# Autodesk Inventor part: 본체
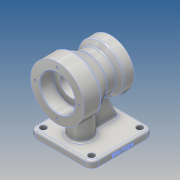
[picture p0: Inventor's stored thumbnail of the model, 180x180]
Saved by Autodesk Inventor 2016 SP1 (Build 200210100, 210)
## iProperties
Created: 2019-01
Part Number: 본체
Material: 알루미늄 6061
Document SubType Name: Modeling
Designer: Administrator
Density: 2.7 g/cm^3
Appearance: 알루미늄 - 평지
Mass: 898.821 g
Surface Area: 600.961 cm^2
Volume: 332.897 cm^3
Author: Administrator
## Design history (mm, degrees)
sketch "스케치2"
  geometry: L1 (0, 0)-(-80, 0); L2 (0, 0)-(0, 40); L3 (0, 40)-(-25, 40); L4 (-25, 40)-(-45.785, 28); L5 (-45.785, 28)-(-59.126, 28); L6 (-59.126, 28)-(-65, 35); L7 (-65, 35)-(-80, 35); L8 (-80, 35)-(-80, 0)
  constraints: 16 end point, 2 parallel, 2 perpendicular, 1 horizontal, 1 vertical
  dimensions: "d0" = 80 distance of L1.start L1.end; "d1" = 80 diameter of L3 L1; "d2" = 30 deg angle of L5 L4; "d3" = 50 deg angle of L5 L6; "d4" = 25 distance of L2.end L3.end; "d5" = 56 diameter of L5 L1; "d6" = 15 distance of L6.end L7.end; "d7" = 70 diameter of L7 L1
revolve "회전1" sketch "스케치2" stored, may be unused: angle "d8" = 90 deg
node "작업 평면1"
sketch "스케치4"
  geometry: L1 (5, 46)-(97, 46); L2 (97, 46)-(97, -46); L3 (97, -46)-(5, -46); L4 (5, -46)-(5, 46); 2 further points
  constraints: 8 end point, 2 parallel, 1 horizontal, 1 horizontal alignment, 1 midpoint, 1 perpendicular
  dimensions: "d12" = 92 distance of L2.end L3.end; "d13" = 92 distance of L1.end L2.end; "d14" = 5 distance from line of point (0, 0) L4
extrude "돌출1" join sketch "스케치4" distance "d15" = 10; taper "d16" = 0 deg
sketch "스케치5"
  geometry: L1 (50.199, 5)-(87, 5); L2 (87, 5)-(87, -5); L3 (87, -5)-(50.199, -5); L4 (5, -46)-(5, 46) reference; L5 (97, 46)-(97, -46) reference; A1 r 16 centre (35, 0) between (50.199, 5) and (50.199, -5); 2 further points
  constraints: 6 end point, 2 horizontal alignment, 2 point on circle, 1 centre point, 1 horizontal, 1 midpoint, 1 parallel, 1 perpendicular
  dimensions: "d17" = 32 diameter of A1; "d18" = 10 distance between parallel lines of L3 L1; "d19" = 30 distance from line of A1.centre L4; "d20" = 10 distance between parallel lines of L2 L5
extrude "돌출2" join sketch "스케치5" distance "d21" = 45; taper "d22" = 0 deg
feature "면 기울기2" dims angle "d26" = 25 deg
sketch "스케치7"
  geometry: L1 (0, 0)-(-80, 0); L2 (-80, -35)-(-80, 35) reference; L3 (0, -40)-(0, 40) reference; L4 (0, 26)-(-19, 26); L5 (-20, 25)-(-20, 16); L6 (-20, 16)-(-63, 16); L7 (-63, 16)-(-63, 19.4); L8 (-63.6, 20)-(-80, 20); L9 (0, 26)-(0, 0); L10 (-80, 20)-(-80, 0); A1 r 1 centre (-19, 25) between (-19, 26) and (-20, 25); A2 r 0.6 centre (-63.6, 19.4) between (-63, 19.4) and (-63.6, 20); 2 further points
  constraints: 16 end point, 6 point on line, 4 perpendicular, 4 point on circle, 4 tangent, 2 centre point, 1 collinear, 1 horizontal, 1 midpoint, 1 parallel
  dimensions: "d27" = 52 diameter of L4 L1; "d28" = 20 distance of L4.start point (-20, 26); "d29" = 32 diameter of L6 L1; "d30" = 17 distance of point (-63, 20) L8.end; "d31" = 40 diameter of L8 L1; "d32" = 1 radius of A1; "d33" = 0.6 radius of A2
revolve "회전2" sketch "스케치7" stored, may be unused: angle "d34" = 90 deg
sketch "스케치8" dims "d35" = 66
  geometry: 3 further points
  constraints: 2 horizontal alignment, 1 coincident, 2 other
hole "구멍1" sketch "스케치8" at (33, 0) diameter "d36" = 3.242; stored, may be unused: countersink angle "d40" = 90 deg, drill point angle "d42" = 118 deg; dims "d37" = 9, "d38" = 4, "d39" = 2, "d41" = 11
sketch "스케치9" dims "d46" = 55
  geometry: 3 further points
  constraints: 2 horizontal alignment, 1 coincident, 2 other
hole "구멍2" sketch "스케치9" at (-27.5, 0) diameter "d47" = 3.242; stored, may be unused: countersink angle "d51" = 90 deg, drill point angle "d53" = 118 deg; dims "d48" = 9, "d49" = 4, "d50" = 2, "d52" = 11
fillet "모깎기1" dims "d57" = 10, "d58" = 3, "d59" = 3, "d60" = 3, "d61" = 3
sketch "스케치10"
  geometry: L1 (97, 36)-(97, -36) reference; L2 (87, -46)-(15, -46) reference; L3 (5, -36)-(5, 36) reference; L4 (15, 46)-(87, 46) reference; C1 r 4.5 at (15, 36); C2 r 4.5 at (87, 36); C3 r 4.5 at (87, -36); C4 r 4.5 at (15, -36); A1 r 10 centre (87, 36) between (97, 36) and (87, 46) reference; A2 r 10 centre (87, -36) between (87, -46) and (97, -36) reference; A3 r 10 centre (15, -36) between (5, -36) and (15, -46) reference; A4 r 10 centre (15, 36) between (15, 46) and (5, 36) reference; 1 further point
  constraints: 4 centre point, 4 coincident
  dimensions: "d62" = 9 diameter of C1; "d63" = 9 diameter of C2; "d64" = 9 diameter of C3; "d65" = 9 diameter of C4
extrude "돌출3" cut sketch "스케치10" stored distance "d66" = 45; taper "d67" = 0 deg
chamfer "모따기1" distance "d68" = 1; stored, may be unused: second distance "d69" = 2, angle "d70" = 45 deg
fillet "모깎기2" dims "d71" = 3
sketch "스케치11"
  geometry: L1 (72, 0)-(0, 0) reference; L2 (-10, 7)-(-10, 0) reference; 2 further points
  constraints: 1 other
  dimensions: "d72" = 4 distance from line of L1 point (36, 4); "d73" = 46 distance from line of L2 point (36, 4)
feature "엠보싱1" sketch "스케치11" dims "d17" = 32, "d18" = 10, "d19" = 30, "d20" = 10, "d74" = 0.5, "d75" = 0
node "솔리드1"
pattern_circular "원형 패턴1" dims angle "d44" = 360 deg
pattern_circular "원형 패턴2" dims angle "d55" = 360 deg
node "투영된 루프1"
